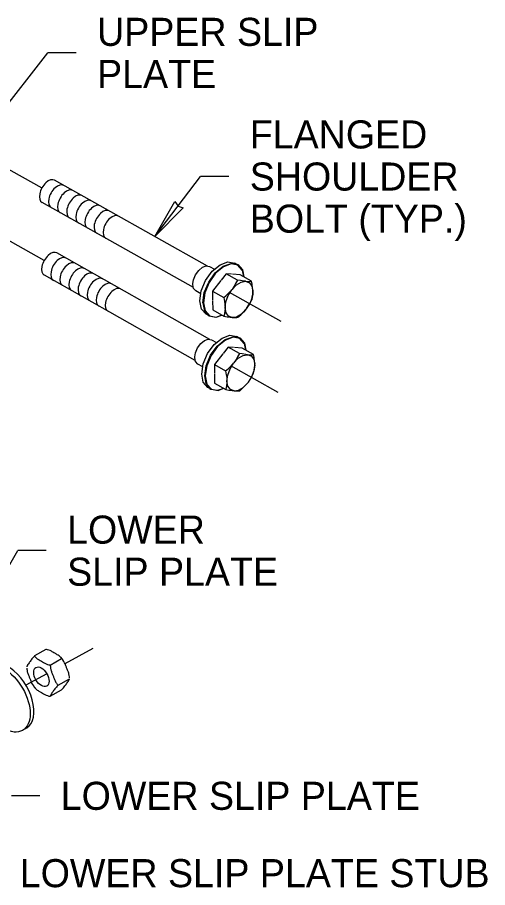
# Model space of a CAD drawing. Extents: x 99862 to 103151, y 99997 to 117076.
# Drawn here: x 100446.4 to 100714.1, y 112640.7 to 113136.6 of the extents above; entities that cross this region are included whole.
import ezdxf

# ---------------------------------------------------------------- set-up
doc = ezdxf.new("R2010")
doc.units = 0
for name, color, linetype in [('Level 13', 7, 'Continuous'), ('Level 15', 7, 'Continuous'), ('Level 20', 7, 'Continuous'), ('Level 3', 7, 'Continuous'), ('Level 5', 7, 'Continuous'), ('Level 9', 7, 'Continuous')]:
    doc.layers.add(name, color=color, linetype=linetype)

msp = doc.modelspace()

# ---------------------------------------------------------------- linework, layer by layer
at = {"layer": 'Level 13'}
for p, q in [((100554.71, 112994.87), (100467.58, 113043.81)), ((100546.61, 112982.71), (100460.45, 113031.11)), ((100555.99, 112953.05), (100468.89, 113002.36)), ((100547.66, 112941.02), (100461.72, 112989.68)), ((100462.63, 112776.39), (100456.2, 112772.67)), ((100465.12, 112767.52), (100471.55, 112771.24)), ((100469.58, 112756.03), (100476.02, 112759.74)), ((100465.12, 112749.68), (100471.55, 112753.4))]:
    msp.add_line(p, q, dxfattribs=at)
for centre, major_axis, start_param, end_param in [((100464.02, 113037.46), (3.57, 6.35), 6.283173, 9.424785), ((100469.2, 113034.55), (3.57, 6.35), 6.283174, 9.424783), ((100474.39, 113031.63), (3.57, 6.35), 6.283172, 9.424785), ((100479.58, 113028.72), (3.57, 6.35), 6.283179, 9.424784), ((100484.77, 113025.8), (3.57, 6.35), 6.283177, 9.424782), ((100489.96, 113022.89), (3.57, 6.35), 6.283174, 9.424785), ((100495.14, 113019.97), (3.57, 6.35), 6.283176, 9.424783), ((100500.33, 113017.06), (3.57, 6.35), 6.283178, 9.42478), ((100465.3, 112996.02), (3.59, 6.34), 6.283173, 9.424785), ((100470.48, 112993.09), (3.59, 6.34), 6.283174, 9.424783), ((100475.66, 112990.16), (3.59, 6.34), 6.283172, 9.424785), ((100480.84, 112987.23), (3.59, 6.34), 6.283179, 9.424784), ((100486.02, 112984.29), (3.59, 6.34), 6.283177, 9.424782), ((100491.2, 112981.36), (3.59, 6.34), 6.283174, 9.424785), ((100496.37, 112978.43), (3.59, 6.34), 6.283176, 9.424783), ((100501.55, 112975.5), (3.59, 6.34), 6.283178, 9.42478), ((100441.05, 112749.52), (-10.41, 18.04), 3.035348, 6.38194)]:
    msp.add_ellipse(centre, major_axis=major_axis, ratio=0.57735, start_param=start_param, end_param=end_param, dxfattribs=at)
for centre, major_axis in [((100438.91, 112748.3), (-10.41, 18.04)), ((100460.01, 112760.8), (-3.09, 5.34))]:
    msp.add_ellipse(centre, major_axis=major_axis, ratio=0.57735, dxfattribs=at)
for points, degree in [([(100471.19, 112771.81), (100470.42, 112772.69), (100468.93, 112773.49), (100467.73, 112774.18), (100466.52, 112774.89), (100465.11, 112775.76), (100463.28, 112776.28), (100462.95, 112776.35), (100462.63, 112776.39)], 3), ([(100456.2, 112772.67), (100455.97, 112772.46), (100455.76, 112772.24), (100454.61, 112771.01), (100453.93, 112770), (100453.32, 112769.13), (100452.72, 112768.26), (100451.93, 112767.19), (100451.73, 112766.54), (100451.72, 112766.48), (100451.72, 112766.43)], 3), ([(100456.2, 112772.67), (100456.26, 112772.49), (100456.39, 112772.3), (100457.28, 112771.24), (100458.8, 112770.43), (100460.02, 112769.73), (100461.23, 112769.02), (100462.64, 112768.15), (100464.47, 112767.64), (100464.8, 112767.56), (100465.12, 112767.52)], 3), ([(100472.26, 112770.48), (100471.92, 112770.93), (100471.57, 112771.38), (100471.19, 112771.82)], 2), ([(100476.03, 112760.27), (100476.03, 112760.43), (100476.01, 112760.58), (100475.82, 112762.44), (100475.03, 112764.29), (100474.43, 112765.86), (100473.83, 112767.38), (100473.18, 112769.23), (100472.26, 112770.48)], 3), ([(100451.72, 112765.8), (100451.72, 112765.64), (100451.74, 112765.49), (100451.93, 112763.63), (100452.72, 112761.78), (100453.32, 112760.21), (100453.92, 112758.69), (100454.57, 112756.84), (100455.49, 112755.59)], 3), ([(100465.12, 112767.52), (100465.09, 112767.2), (100465.1, 112766.85), (100465.31, 112764.83), (100466.1, 112762.98), (100466.71, 112761.4), (100467.32, 112759.83), (100467.99, 112757.92), (100469.14, 112756.44), (100469.35, 112756.2), (100469.58, 112756.03)], 3), ([(100455.49, 112755.59), (100455.83, 112755.14), (100456.18, 112754.69), (100456.56, 112754.26)], 2), ([(100469.58, 112756.03), (100469.35, 112755.82), (100469.14, 112755.59), (100467.99, 112754.36), (100467.32, 112753.35), (100466.71, 112752.48), (100466.1, 112751.62), (100465.31, 112750.55), (100465.1, 112749.85), (100465.09, 112749.75), (100465.12, 112749.68)], 3), ([(100471.55, 112753.4), (100471.78, 112753.61), (100471.99, 112753.83), (100473.14, 112755.07), (100473.82, 112756.07), (100474.43, 112756.94), (100475.03, 112757.81), (100475.82, 112758.88), (100476.02, 112759.53), (100476.03, 112759.59), (100476.03, 112759.64)], 3), ([(100456.56, 112754.26), (100457.33, 112753.38), (100458.82, 112752.58), (100460.02, 112751.89), (100461.23, 112751.18), (100462.64, 112750.31), (100464.47, 112749.79), (100464.8, 112749.72), (100465.12, 112749.68)], 3)]:
    msp.add_open_spline(points, degree=degree, dxfattribs=at)
at = {"layer": 'Level 15'}
for p, q in [((100414.55, 113053.42), (100463.76, 113116.4)), ((100479.76, 113116.4), (100463.76, 113116.4)), ((100461.64, 112998.09), (100325.22, 113075.2)), ((100524.64, 113011.76), (100550.72, 113045.95)), ((100566.72, 113045.95), (100550.72, 113045.95)), ((100594.87, 112922.8), (100567.98, 112938)), ((100400.81, 112753.24), (100446.69, 112832.7)), ((100462.69, 112832.7), (100446.69, 112832.7)), ((100489.39, 112777.03), (100473.46, 112768.28)), ((100463.1, 112762.59), (100451.16, 112756.03)), ((100459.06, 112692.97), (100443.06, 112692.97))]:
    msp.add_line(p, q, dxfattribs=at)
for points in [[(100325.29, 113114.94), (100460.35, 113039.52)], [(100567.04, 112979.94), (100596.41, 112963.54)]]:
    msp.add_lwpolyline(points, dxfattribs=at)
msp.add_lwpolyline([(100524.64, 113011.76), (100536.11, 113031.72), (100537.85, 113029.07), (100540.86, 113028.1)], close=True, dxfattribs=at)
at = {"layer": 'Level 3'}
for p, q in [((100563.69, 112994.43), (100563.69, 112994.48)), ((100568.11, 112996.05), (100568.12, 112996.11)), ((100571.87, 112995.37), (100571.91, 112995.43)), ((100574.46, 112992.55), (100571.91, 112995.43)), ((100559.3, 112990.76), (100559.28, 112990.8)), ((100574.49, 112992.81), (100575.31, 112988.75)), ((100555.6, 112985.61), (100555.57, 112985.62)), ((100572.13, 112986.85), (100572.02, 112986.81)), ((100553.16, 112979.74), (100553.12, 112979.74)), ((100551.97, 112974.01), (100552.93, 112969.29)), ((100555.53, 112966.36), (100552.93, 112969.29)), ((100555.83, 112966.57), (100555.79, 112966.52)), ((100559.59, 112965.9), (100559.58, 112965.84)), ((100569.26, 112954.26), (100569.27, 112954.32)), ((100573.02, 112953.57), (100573.05, 112953.62)), ((100575.6, 112950.73), (100573.05, 112953.62)), ((100560.43, 112949), (100560.41, 112949.04)), ((100564.84, 112952.65), (100564.83, 112952.71)), ((100575.63, 112950.99), (100576.44, 112946.94)), ((100556.72, 112943.86), (100556.68, 112943.88)), ((100573.24, 112945.04), (100573.14, 112945.01)), ((100554.25, 112938), (100554.21, 112938)), ((100553.42, 112932.33), (100553.37, 112932.3)), ((100556.58, 112924.62), (100553.99, 112927.55)), ((100556.88, 112924.83), (100556.84, 112924.77)), ((100560.64, 112924.14), (100560.62, 112924.07))]:
    msp.add_line(p, q, dxfattribs=at)
for points in [[(100559.07, 112991.03), (100563.55, 112994.77), (100563.55, 112994.77)], [(100563.7, 112994.43), (100563.69, 112994.48), (100559.28, 112990.8)], [(100563.55, 112994.77), (100568.05, 112996.42), (100568.05, 112996.42)], [(100568.11, 112996.04), (100568.12, 112996.11), (100563.69, 112994.48)], [(100568.05, 112996.42), (100571.9, 112995.73), (100571.9, 112995.73)], [(100571.88, 112995.36), (100571.91, 112995.43), (100568.12, 112996.11)], [(100571.9, 112995.73), (100574.49, 112992.81), (100574.49, 112992.81)], [(100555.3, 112985.77), (100559.07, 112991.03), (100559.07, 112991.03)], [(100559.31, 112990.77), (100559.28, 112990.8), (100555.57, 112985.62)], [(100574.42, 112992.49), (100574.46, 112992.55), (100575.22, 112988.8)], [(100552.81, 112979.79), (100555.3, 112985.77), (100555.3, 112985.77)], [(100555.61, 112985.62), (100555.57, 112985.62), (100553.12, 112979.74)], [(100551.98, 112974.01), (100551.97, 112974.01), (100552.81, 112979.79), (100552.81, 112979.8)], [(100553.16, 112979.76), (100553.12, 112979.74), (100552.3, 112974.04)], [(100552.34, 112974.08), (100552.3, 112974.04), (100553.24, 112969.4)], [(100553.24, 112969.4), (100555.79, 112966.52)], [(100559.37, 112965.67), (100555.53, 112966.36), (100555.53, 112966.36)], [(100555.82, 112966.58), (100555.79, 112966.52), (100559.58, 112965.84)], [(100562.85, 112966.95), (100559.37, 112965.67), (100559.37, 112965.67)], [(100559.58, 112965.9), (100559.58, 112965.84), (100562.76, 112967)], [(100564.7, 112953), (100569.2, 112954.63), (100569.2, 112954.63)], [(100569.26, 112954.25), (100569.27, 112954.32), (100564.83, 112952.71)], [(100569.2, 112954.63), (100573.04, 112953.93), (100573.04, 112953.93)], [(100573.03, 112953.56), (100573.05, 112953.62), (100569.27, 112954.32)], [(100573.04, 112953.93), (100575.63, 112950.99), (100575.63, 112950.99)], [(100556.41, 112944.03), (100560.2, 112949.27), (100560.2, 112949.27)], [(100560.44, 112949.01), (100560.41, 112949.04), (100556.68, 112943.88)], [(100560.2, 112949.27), (100564.7, 112953), (100564.7, 112953)], [(100564.84, 112952.66), (100564.83, 112952.71), (100560.41, 112949.04)], [(100575.56, 112950.68), (100575.6, 112950.73), (100576.35, 112946.99)], [(100556.72, 112943.87), (100556.68, 112943.88), (100554.21, 112938)], [(100554.26, 112938.02), (100554.21, 112938), (100553.37, 112932.3)], [(100553.09, 112932.28), (100553.08, 112932.27), (100553.08, 112932.27), (100553.05, 112932.27)], [(100553.42, 112932.34), (100553.37, 112932.3), (100554.3, 112927.66)], [(100554.3, 112927.66), (100556.84, 112924.77)], [(100560.42, 112923.91), (100556.58, 112924.62), (100556.58, 112924.62)], [(100556.87, 112924.83), (100556.84, 112924.77), (100560.62, 112924.07)], [(100563.9, 112925.18), (100560.42, 112923.91), (100560.42, 112923.91)], [(100560.63, 112924.14), (100560.62, 112924.07), (100563.81, 112925.23)]]:
    msp.add_lwpolyline(points, dxfattribs=at)
at = {"layer": 'Level 5'}
for p, q in [((100571.5, 112995.8), (100570.12, 112996.58)), ((100572.65, 112954), (100571.27, 112954.78)), ((100554.07, 112927.58), (100554.05, 112927.6))]:
    msp.add_line(p, q, dxfattribs=at)
for points in [[(100550.82, 112979.13), (100547.96, 112980.74), (100546.72, 112982.14), (100546.26, 112984.38), (100546.27, 112984.93), (100546.66, 112987.12), (100547.85, 112989.96), (100549.65, 112992.45), (100551.79, 112994.22), (100553.94, 112995), (100555.78, 112994.66), (100558.64, 112993.05)], [(100555.26, 112966.66), (100553.78, 112967.49), (100551.19, 112970.41), (100550.24, 112975.09), (100551.07, 112980.83), (100553.56, 112986.75), (100557.32, 112991.96), (100561.79, 112995.65), (100566.29, 112997.28), (100570.12, 112996.58)], [(100562.86, 112966.94), (100562.84, 112966.93), (100562.55, 112966.84)], [(100556.31, 112924.92), (100554.84, 112925.75), (100552.25, 112928.67), (100551.32, 112933.36), (100552.17, 112939.1), (100554.67, 112945.01), (100558.46, 112950.21), (100562.94, 112953.89), (100567.44, 112955.49), (100571.27, 112954.78)], [(100551.92, 112937.4), (100549.05, 112939.02), (100547.82, 112940.42), (100547.37, 112942.66), (100547.39, 112943.22), (100547.78, 112945.41), (100548.98, 112948.24), (100550.79, 112950.72), (100552.93, 112952.48), (100555.09, 112953.25), (100556.92, 112952.91), (100559.78, 112951.29)], [(100553.96, 112927.71), (100553.96, 112927.71), (100553.02, 112932.39), (100553.87, 112938.13), (100556.38, 112944.05), (100560.16, 112949.24), (100560.69, 112949.68)], [(100563.92, 112925.17), (100563.89, 112925.16), (100563.61, 112925.07)]]:
    msp.add_lwpolyline(points, dxfattribs=at)
at = {"layer": 'Level 9'}
for p, q in [((100571.71, 112986.92), (100565.3, 112990.52)), ((100571.71, 112986.92), (100565.3, 112990.52)), ((100572.83, 112945.11), (100566.43, 112948.74)), ((100572.83, 112945.11), (100566.43, 112948.74))]:
    msp.add_line(p, q, dxfattribs=at)
for points in [[(100568.38, 112990.28), (100565.3, 112990.52), (100562.41, 112986.83)], [(100568.38, 112990.28), (100565.3, 112990.52), (100562.41, 112986.83)], [(100580.45, 112980.84), (100580.45, 112980.96), (100580.07, 112984.24), (100580.02, 112984.66), (100579.68, 112986.3), (100573.27, 112989.9), (100568.79, 112990.25)], [(100580.45, 112980.84), (100580.45, 112980.96), (100580.07, 112984.24), (100580.02, 112984.66), (100579.68, 112986.3), (100573.27, 112989.9), (100568.79, 112990.25)], [(100562.27, 112986.65), (100557.46, 112980.52), (100557.52, 112975.63)], [(100569.81, 112983.36), (100568.59, 112981.63), (100571.06, 112984.13), (100573.74, 112985.74), (100576.24, 112986.22), (100575.34, 112986.31), (100573.35, 112986.64), (100571.71, 112986.92), (100570.64, 112984.92), (100569.81, 112983.36)], [(100569.81, 112983.36), (100568.59, 112981.63), (100571.06, 112984.13), (100573.74, 112985.74), (100576.24, 112986.22), (100575.34, 112986.31), (100573.35, 112986.64), (100571.71, 112986.92), (100570.64, 112984.92), (100569.81, 112983.36)], [(100576.24, 112986.22), (100576.58, 112986.19), (100577.04, 112986.17), (100578.64, 112986.2), (100579.03, 112986.21), (100579.68, 112986.3)], [(100576.24, 112986.22), (100576.58, 112986.19), (100577.04, 112986.17), (100578.64, 112986.2), (100579.03, 112986.21), (100579.68, 112986.3)], [(100576.58, 112986.19), (100578.57, 112985.38), (100579.92, 112983.51), (100580.45, 112980.84)], [(100576.58, 112986.19), (100578.57, 112985.38), (100579.92, 112983.51), (100580.45, 112980.84)], [(100557.46, 112980.52), (100563.87, 112976.92), (100565.27, 112978.11), (100565.65, 112978.51), (100568.23, 112981.17), (100568.41, 112981.4), (100568.59, 112981.63)], [(100557.46, 112980.52), (100563.87, 112976.92), (100565.27, 112978.11), (100565.65, 112978.51), (100568.23, 112981.17), (100568.41, 112981.4), (100568.59, 112981.63)], [(100568.69, 112965.6), (100566.62, 112966.36), (100565.18, 112968.29), (100564.64, 112971.15), (100565.07, 112974.59), (100566.41, 112978.19), (100568.41, 112981.4)], [(100568.69, 112965.6), (100566.62, 112966.36), (100565.18, 112968.29), (100564.64, 112971.15), (100565.07, 112974.59), (100566.41, 112978.19), (100568.41, 112981.4)], [(100580.46, 112980.34), (100579.99, 112977.07), (100578.69, 112973.62), (100576.74, 112970.47)], [(100580.46, 112980.34), (100579.99, 112977.07), (100578.69, 112973.62), (100576.74, 112970.47)], [(100580.45, 112980.84), (100580.46, 112980.34), (100580.38, 112978.76), (100580.11, 112977.31), (100579.8, 112975.69)], [(100579.8, 112975.69), (100580.11, 112977.31), (100580.38, 112978.76), (100580.46, 112980.34), (100580.45, 112980.84)], [(100557.52, 112975.24), (100557.58, 112969.91), (100563.99, 112966.31), (100565.83, 112966), (100567.62, 112965.7), (100568.69, 112965.6)], [(100563.87, 112976.92), (100564.24, 112974.77), (100564.52, 112973.22), (100564.63, 112971.16), (100564.64, 112970.85), (100564.34, 112967.95), (100564.3, 112967.58), (100563.99, 112966.31)], [(100563.87, 112976.92), (100564.24, 112974.77), (100564.52, 112973.22), (100564.63, 112971.16), (100564.64, 112970.85), (100564.34, 112967.95), (100564.3, 112967.58), (100563.99, 112966.31)], [(100576.46, 112970.11), (100576.74, 112970.47), (100576.87, 112970.63), (100578.77, 112973.68), (100579.05, 112974.13), (100579.8, 112975.69)], [(100576.46, 112970.11), (100576.74, 112970.47), (100576.87, 112970.63), (100578.77, 112973.68), (100579.05, 112974.13), (100579.8, 112975.69)], [(100576.46, 112970.11), (100575.1, 112968.56), (100573.6, 112967.18), (100571.96, 112965.69), (100571.31, 112965.6), (100570.85, 112965.57), (100570.82, 112965.56), (100568.69, 112965.6)], [(100568.69, 112965.6), (100571.21, 112966.01), (100573.94, 112967.59), (100576.46, 112970.11)], [(100568.69, 112965.6), (100571.21, 112966.01), (100573.94, 112967.59), (100576.46, 112970.11)], [(100568.69, 112965.6), (100570.82, 112965.56), (100570.85, 112965.57), (100571.31, 112965.6), (100571.96, 112965.69), (100573.6, 112967.18), (100575.1, 112968.56), (100576.46, 112970.11)], [(100569.51, 112948.49), (100566.43, 112948.74), (100563.53, 112945.06)], [(100563.38, 112944.88), (100558.55, 112938.77), (100558.6, 112933.88)], [(100570.91, 112941.56), (100569.69, 112939.84), (100572.17, 112942.33), (100574.85, 112943.93), (100577.36, 112944.4), (100576.46, 112944.5), (100574.46, 112944.84), (100572.83, 112945.11), (100571.75, 112943.12), (100570.91, 112941.56)], [(100570.91, 112941.56), (100569.69, 112939.84), (100572.17, 112942.33), (100574.85, 112943.93), (100577.36, 112944.4), (100576.46, 112944.5), (100574.46, 112944.84), (100572.83, 112945.11), (100571.75, 112943.12), (100570.91, 112941.56)], [(100581.55, 112939.01), (100581.55, 112939.13), (100581.18, 112942.41), (100581.13, 112942.83), (100580.79, 112944.47), (100574.4, 112948.09), (100569.92, 112948.45)], [(100577.36, 112944.4), (100577.7, 112944.37), (100578.15, 112944.35), (100579.75, 112944.38), (100580.15, 112944.39), (100580.79, 112944.47)], [(100577.36, 112944.4), (100577.7, 112944.37), (100578.15, 112944.35), (100579.75, 112944.38), (100580.15, 112944.39), (100580.79, 112944.47)], [(100577.7, 112944.37), (100579.68, 112943.56), (100581.03, 112941.68), (100581.55, 112939.01)], [(100577.7, 112944.37), (100579.68, 112943.56), (100581.03, 112941.68), (100581.55, 112939.01)], [(100558.55, 112938.77), (100564.95, 112935.15), (100566.36, 112936.33), (100566.74, 112936.73), (100569.33, 112939.38), (100569.51, 112939.61), (100569.69, 112939.84)], [(100558.55, 112938.77), (100564.95, 112935.15), (100566.36, 112936.33), (100566.74, 112936.73), (100569.33, 112939.38), (100569.51, 112939.61), (100569.69, 112939.84)], [(100569.74, 112923.81), (100567.67, 112924.57), (100566.24, 112926.51), (100565.71, 112929.37), (100566.15, 112932.81), (100567.5, 112936.41), (100569.51, 112939.61)], [(100569.74, 112923.81), (100567.67, 112924.57), (100566.24, 112926.51), (100565.71, 112929.37), (100566.15, 112932.81), (100567.5, 112936.41), (100569.51, 112939.61)], [(100580.88, 112933.86), (100581.2, 112935.48), (100581.47, 112936.93), (100581.55, 112938.51), (100581.55, 112939.01)], [(100564.95, 112935.15), (100565.32, 112932.99), (100565.59, 112931.44), (100565.69, 112929.38), (100565.71, 112929.07), (100565.39, 112926.17), (100565.35, 112925.8), (100565.04, 112924.53)], [(100564.95, 112935.15), (100565.32, 112932.99), (100565.59, 112931.44), (100565.69, 112929.38), (100565.71, 112929.07), (100565.39, 112926.17), (100565.35, 112925.8), (100565.04, 112924.53)], [(100577.52, 112928.29), (100577.8, 112928.65), (100577.93, 112928.82), (100579.85, 112931.86), (100580.13, 112932.3), (100580.88, 112933.86)], [(100581.55, 112938.51), (100581.08, 112935.24), (100579.77, 112931.79), (100577.8, 112928.65)], [(100581.55, 112938.51), (100581.08, 112935.24), (100579.77, 112931.79), (100577.8, 112928.65)], [(100558.6, 112933.49), (100558.64, 112928.15), (100565.04, 112924.53), (100566.87, 112924.22), (100568.67, 112923.92), (100569.74, 112923.81)], [(100569.74, 112923.81), (100572.26, 112924.21), (100574.99, 112925.78), (100577.52, 112928.29)], [(100569.74, 112923.81), (100572.26, 112924.21), (100574.99, 112925.78), (100577.52, 112928.29)], [(100569.74, 112923.81), (100571.87, 112923.77), (100571.9, 112923.77), (100572.36, 112923.8), (100573.01, 112923.89), (100574.65, 112925.38), (100576.16, 112926.75), (100577.52, 112928.29)]]:
    msp.add_lwpolyline(points, dxfattribs=at)

# ---------------------------------------------------------------- texts
at = {"layer": 'Level 20'}
for s, p in [('UPPER SLIP', (100491.76, 113120.4)), ('PLATE', (100491.76, 113096.4)), ('FLANGED', (100578.72, 113061.94)), ('SHOULDER ', (100578.72, 113037.94)), ('BOLT (TYP.)', (100578.72, 113013.94)), ('LOWER', (100474.69, 112836.7)), ('SLIP PLATE', (100474.69, 112812.7)), ('LOWER SLIP PLATE', (100471.06, 112684.98)), ('LOWER SLIP PLATE STUB', (100447.73, 112640.89))]:
    msp.add_text(s, height=16, dxfattribs=at).set_placement(p)

doc.saveas('drawing.dxf')
